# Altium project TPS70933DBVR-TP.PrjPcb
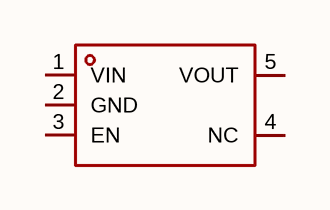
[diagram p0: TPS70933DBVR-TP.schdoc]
1 sheet, 1 parts. Net scope: global (net labels, ports and power ports of the same name join across sheets).

## Sheet TPS70933DBVR-TP.schdoc
size 127 x 101 mm

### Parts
U?  tps70933dbvr-tp  [SOT-23-5_L3.0-W1.7-P0.95-LS2.8-BR]  (value not drawn)

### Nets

Not connected (* = marked no-connect by the designer): U? 1(VIN) 2(GND) 3(EN) 4(NC) 5(VOUT)

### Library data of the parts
U? = tps70933dbvr-tp: 输出极性:正极;工作电压:36V;输出电压:3.3V;输出电流:200mA;电源纹波抑制比(PSRR):70dB@(100Hz);输出类型:固定;; Manufacturer: TECH PUBLIC(台舟); AddInBom: yes; ModelId: 0a2a1b8f50944f73965918ad6e5fe167; ModelName: SOT-23-5_L2.9-W1.6-H1.1-LS2.8-P0.95; ModelTransform: 114.173,109.636,0,180,0,0,0,0,0; Output Configuration: 正极; Voltage - Supply: 36V; Output Voltage: 3.3V; Output Current: 200mA; Voltage Dropout: 750mV@(100mA); standby current: 2uA; Output Type: 固定; Number of Outputs: 1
